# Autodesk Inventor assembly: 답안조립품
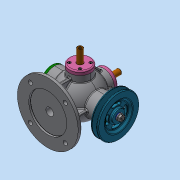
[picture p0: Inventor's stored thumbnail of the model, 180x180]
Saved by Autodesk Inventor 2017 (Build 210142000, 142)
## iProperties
Part Number: 답안조립품
Material: 일반
Document SubType Name: Assembly
Designer: MRC
Author: MRC
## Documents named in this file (17)
- C:\Users\MRC\Desktop\620909V1005\620909V1005\답안조립품.iam
- C:\Users\MRC\Desktop\620909V1005\620909V1005\본체.ipt
- C:\Users\MRC\Desktop\620909V1005\620909V1005\V-벨트풀리.ipt
- C:\Users\MRC\Desktop\620909V1005\620909V1005\너트-M8x1.ipt
- C:\Users\MRC\Desktop\620909V1005\620909V1005\뒤커버.ipt
- C:\Users\MRC\Desktop\620909V1005\620909V1005\베어링- 6202.ipt
- C:\Users\MRC\Desktop\620909V1005\620909V1005\본체커버.ipt
- C:\Users\MRC\Desktop\620909V1005\620909V1005\볼트 M4x0.7.ipt
- C:\Users\MRC\Desktop\620909V1005\620909V1005\슬라이드 커버.ipt
- C:\Users\MRC\Desktop\620909V1005\620909V1005\슬라이드.ipt
- C:\Users\MRC\Desktop\620909V1005\620909V1005\앞커버.ipt
- C:\Users\MRC\Desktop\620909V1005\620909V1005\오일실.ipt
- C:\Users\MRC\Desktop\620909V1005\620909V1005\와셔 8x17.ipt
- C:\Users\MRC\Desktop\620909V1005\620909V1005\축.ipt
- C:\Users\MRC\Desktop\620909V1005\620909V1005\키-4x4.ipt
- C:\Users\MRC\Desktop\620909V1005\620909V1005\가변스프링1.ipt
- C:\Users\MRC\Desktop\620909V1005\620909V1005\가변스프링2.ipt
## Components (20 placed, 4 different names)
1. V-벨트풀리:1
2. M4x0.7x12:5
3. 가변스프링1:1
4. 가변스프링2:1
5. M4x0.7x12:4
6. M4x0.7x12:6
7. M4x0.7x12:7
8. M4x0.7x12:8
9. M4x0.7x12:1
10. M4x0.7x12:9
11. M4x0.7x12:10
12. M4x0.7x12:11
13. M4x0.7x12:2
14. M4x0.7x12:12
15. M4x0.7x12:13
16. M4x0.7x12:14
17. M4x0.7x12:3
18. M4x0.7x12:15
19. M4x0.7x12:16
20. M4x0.7x12:17
